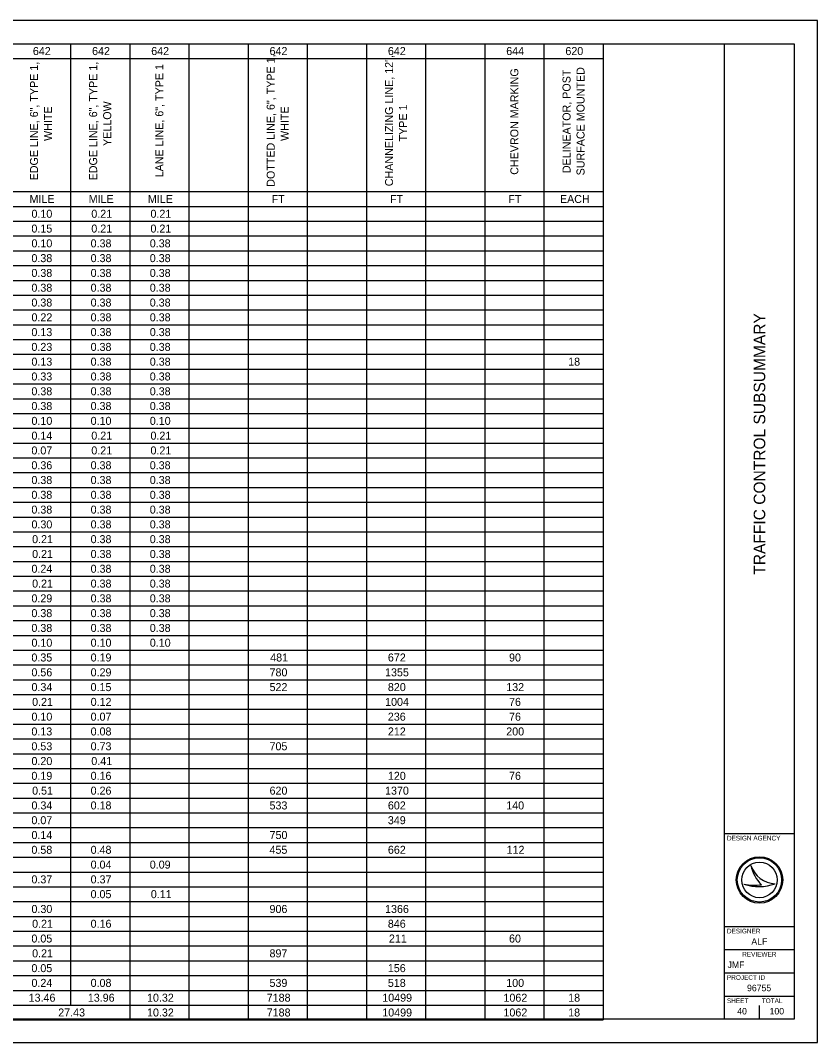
# Model space of a CAD drawing. Extents: x 0 to 34, y 0 to 22.
# Drawn here: x 16.84 to 34, y 0 to 22 of the extents above; entities that cross this region are included whole.
import ezdxf

# ---------------------------------------------------------------- set-up
doc = ezdxf.new("R2010")
doc.units = 0
for name, color, linetype in [('Default', 7, 'Continuous'), ('SH_Border', 7, 'Continuous'), ('SH_Cut_Line', 7, 'Continuous'), ('SH_Data', 7, 'Continuous')]:
    doc.layers.add(name, color=color, linetype=linetype)

msp = doc.modelspace()

# ---------------------------------------------------------------- linework, layer by layer
at = {"layer": 'Default'}
for p, q in [((1.5, 21.5), (29.385, 21.5)), ((17.924, 21.5), (17.924, 1.124)), ((19.197, 21.5), (19.197, 1.124)), ((20.471, 21.5), (20.471, 1.124)), ((21.744, 21.5), (21.744, 1.124)), ((23.018, 21.5), (23.018, 1.124)), ((24.291, 21.5), (24.291, 1.124)), ((25.565, 21.5), (25.565, 1.124)), ((26.838, 21.5), (26.838, 1.124)), ((28.112, 21.5), (28.112, 1.124)), ((29.385, 21.5), (29.385, 1.124)), ((9.01, 21.182), (29.385, 21.182)), ((9.01, 18.316), (29.385, 18.316)), ((1.5, 17.998), (29.385, 17.998)), ((10.283, 17.68), (29.385, 17.68)), ((10.283, 17.361), (29.385, 17.361)), ((10.283, 17.043), (29.385, 17.043)), ((10.283, 16.724), (29.385, 16.724)), ((10.283, 16.406), (29.385, 16.406)), ((10.283, 16.088), (29.385, 16.088)), ((10.283, 15.769), (29.385, 15.769)), ((10.283, 15.451), (29.385, 15.451)), ((10.283, 15.133), (29.385, 15.133)), ((10.283, 14.814), (29.385, 14.814)), ((10.283, 14.496), (29.385, 14.496)), ((10.283, 14.178), (29.385, 14.178)), ((10.283, 13.859), (29.385, 13.859)), ((10.283, 13.541), (29.385, 13.541)), ((10.283, 13.222), (29.385, 13.222)), ((10.283, 12.904), (29.385, 12.904)), ((10.283, 12.586), (29.385, 12.586)), ((10.283, 12.267), (29.385, 12.267)), ((10.283, 11.949), (29.385, 11.949)), ((10.283, 11.631), (29.385, 11.631)), ((10.283, 11.312), (29.385, 11.312)), ((10.283, 10.994), (29.385, 10.994)), ((10.283, 10.675), (29.385, 10.675)), ((10.283, 10.357), (29.385, 10.357)), ((10.283, 10.039), (29.385, 10.039)), ((10.283, 9.72), (29.385, 9.72)), ((10.283, 9.402), (29.385, 9.402)), ((10.283, 9.084), (29.385, 9.084)), ((10.283, 8.765), (29.385, 8.765)), ((10.283, 8.447), (29.385, 8.447)), ((10.283, 8.129), (29.385, 8.129)), ((10.283, 7.81), (29.385, 7.81)), ((10.283, 7.492), (29.385, 7.492)), ((10.283, 7.173), (29.385, 7.173)), ((10.283, 6.855), (29.385, 6.855)), ((10.283, 6.537), (29.385, 6.537)), ((10.283, 6.218), (29.385, 6.218)), ((10.283, 5.9), (29.385, 5.9)), ((10.283, 5.582), (29.385, 5.582)), ((10.283, 5.263), (29.385, 5.263)), ((10.283, 4.945), (29.385, 4.945)), ((10.283, 4.627), (29.385, 4.627)), ((10.283, 4.308), (29.385, 4.308)), ((10.283, 3.99), (29.385, 3.99)), ((10.283, 3.671), (29.385, 3.671)), ((10.283, 3.353), (29.385, 3.353)), ((10.283, 3.035), (29.385, 3.035)), ((10.283, 2.716), (29.385, 2.716)), ((10.283, 2.398), (29.385, 2.398)), ((10.283, 2.08), (29.385, 2.08)), ((10.283, 1.761), (29.385, 1.761)), ((10.283, 1.443), (29.385, 1.443)), ((1.5, 1.124), (29.385, 1.124)), ((17.924, 1.124), (17.924, 0.806)), ((19.197, 1.124), (19.197, 0.488)), ((20.471, 1.124), (20.471, 0.488)), ((21.744, 1.124), (21.744, 0.488)), ((23.018, 1.124), (23.018, 0.488)), ((24.291, 1.124), (24.291, 0.488)), ((25.565, 1.124), (25.565, 0.488)), ((26.838, 1.124), (26.838, 0.488)), ((28.112, 1.124), (28.112, 0.488)), ((29.385, 1.124), (29.385, 0.488)), ((1.5, 0.806), (29.385, 0.806)), ((1.5, 0.488), (29.385, 0.488))]:
    msp.add_line(p, q, dxfattribs=at)
at = {"layer": 'SH_Border'}
for p, q in [((32, 0.5), (32, 21.5)), ((32, 4.5), (33.5, 4.5)), ((32, 2.5), (33.5, 2.5)), ((32, 2), (33.5, 2)), ((32, 1.5), (33.5, 1.5)), ((32, 1), (33.5, 1))]:
    msp.add_line(p, q, dxfattribs=at)
msp.add_lwpolyline([(1.5, 21.5), (33.5, 21.5), (33.5, 0.5), (1.5, 0.5)], close=True, dxfattribs=at)
at = {"layer": 'SH_Cut_Line'}
msp.add_lwpolyline([(0, 0), (34, 0), (34, 22), (0, 22)], close=True, dxfattribs=at)
at = {"layer": 'SH_Data'}
for p, q in [((32.567, 3.81), (32.567, 3.81)), ((32.417, 3.41), (32.417, 3.41)), ((32.75, 3.5), (32.75, 3.5)), ((33.087, 3.419), (33.087, 3.419)), ((32.375, 0.675), (32.375, 0.675)), ((32.75, 0.5), (32.75, 0.8))]:
    msp.add_line(p, q, dxfattribs=at)
for radius in [0.5, 0.477, 0.477, 0.382]:
    msp.add_circle((32.75, 3.5), radius, dxfattribs=at)
for centre, radius, start, end in [((33.116, 3.998), 0.58, 198.9257, 198.9319), ((33.347, 3.97), 0.796, 191.6379, 191.6421), ((33.116, 3.998), 0.58, 198.9319, 267.1657), ((33.347, 3.97), 0.796, 191.6421, 226.0947), ((32.739, 4.37), 1.013, 251.4576, 290.0832), ((32.648, 4.654), 1.266, 259.4964, 259.4995), ((32.739, 4.37), 1.013, 251.4527, 251.4576), ((32.648, 4.654), 1.266, 259.4995, 276.6672)]:
    msp.add_arc(centre, radius, start, end, dxfattribs=at)

# ---------------------------------------------------------------- texts
at = {"layer": 'Default'}
for s, p in [('642', (17.112, 21.255)), ('642', (18.386, 21.255)), ('642', (19.659, 21.255)), ('642', (22.206, 21.255)), ('642', (24.753, 21.255)), ('644', (27.3, 21.255)), ('620', (28.573, 21.255)), ('MILE', (17.04, 18.071)), ('MILE', (18.314, 18.071)), ('MILE', (19.587, 18.071)), ('FT', (22.251, 18.071)), ('FT', (24.798, 18.071)), ('FT', (27.345, 18.071)), ('EACH', (28.456, 18.071)), ('0.10', (17.082, 17.753)), ('0.21', (18.37, 17.753)), ('0.21', (19.643, 17.753)), ('0.15', (17.081, 17.434)), ('0.21', (18.37, 17.434)), ('0.21', (19.643, 17.434)), ('0.10', (17.082, 17.116)), ('0.38', (18.355, 17.116)), ('0.38', (19.628, 17.116)), ('0.38', (17.081, 16.798)), ('0.38', (18.355, 16.798)), ('0.38', (19.628, 16.798)), ('0.38', (17.081, 16.479)), ('0.38', (18.355, 16.479)), ('0.38', (19.628, 16.479)), ('0.38', (17.081, 16.161)), ('0.38', (18.355, 16.161)), ('0.38', (19.628, 16.161)), ('0.38', (17.081, 15.842)), ('0.38', (18.355, 15.842)), ('0.38', (19.628, 15.842)), ('0.22', (17.082, 15.524)), ('0.38', (18.355, 15.524)), ('0.38', (19.628, 15.524)), ('0.13', (17.081, 15.206)), ('0.38', (18.355, 15.206)), ('0.38', (19.628, 15.206)), ('0.23', (17.081, 14.887)), ('0.38', (18.355, 14.887)), ('0.38', (19.628, 14.887)), ('0.13', (17.081, 14.569)), ('0.38', (18.355, 14.569)), ('0.38', (19.628, 14.569)), ('18', (28.633, 14.569)), ('0.33', (17.081, 14.251)), ('0.38', (18.355, 14.251)), ('0.38', (19.628, 14.251)), ('0.38', (17.081, 13.932)), ('0.38', (18.355, 13.932)), ('0.38', (19.628, 13.932)), ('0.38', (17.081, 13.614)), ('0.38', (18.355, 13.614)), ('0.38', (19.628, 13.614)), ('0.10', (17.082, 13.295)), ('0.10', (18.355, 13.295)), ('0.10', (19.629, 13.295)), ('0.14', (17.082, 12.977)), ('0.21', (18.37, 12.977)), ('0.21', (19.643, 12.977)), ('0.07', (17.081, 12.659)), ('0.21', (18.37, 12.659)), ('0.21', (19.643, 12.659)), ('0.36', (17.081, 12.34)), ('0.38', (18.355, 12.34)), ('0.38', (19.628, 12.34)), ('0.38', (17.081, 12.022)), ('0.38', (18.355, 12.022)), ('0.38', (19.628, 12.022)), ('0.38', (17.081, 11.704)), ('0.38', (18.355, 11.704)), ('0.38', (19.628, 11.704)), ('0.38', (17.081, 11.385)), ('0.38', (18.355, 11.385)), ('0.38', (19.628, 11.385)), ('0.30', (17.082, 11.067)), ('0.38', (18.355, 11.067)), ('0.38', (19.628, 11.067)), ('0.21', (17.096, 10.749)), ('0.38', (18.355, 10.749)), ('0.38', (19.628, 10.749)), ('0.21', (17.096, 10.43)), ('0.38', (18.355, 10.43)), ('0.38', (19.628, 10.43)), ('0.24', (17.082, 10.112)), ('0.38', (18.355, 10.112)), ('0.38', (19.628, 10.112)), ('0.21', (17.096, 9.793)), ('0.38', (18.355, 9.793)), ('0.38', (19.628, 9.793)), ('0.29', (17.081, 9.475)), ('0.38', (18.355, 9.475)), ('0.38', (19.628, 9.475)), ('0.38', (17.081, 9.157)), ('0.38', (18.355, 9.157)), ('0.38', (19.628, 9.157)), ('0.38', (17.081, 8.838)), ('0.38', (18.355, 8.838)), ('0.38', (19.628, 8.838)), ('0.10', (17.082, 8.52)), ('0.10', (18.355, 8.52)), ('0.10', (19.629, 8.52)), ('0.35', (17.081, 8.202)), ('0.19', (18.355, 8.202)), ('481', (22.22, 8.202)), ('672', (24.753, 8.202)), ('90', (27.36, 8.202)), ('0.56', (17.081, 7.883)), ('0.29', (18.355, 7.883)), ('780', (22.206, 7.883)), ('1355', (24.692, 7.883)), ('0.34', (17.082, 7.565)), ('0.15', (18.354, 7.565)), ('522', (22.206, 7.565)), ('820', (24.753, 7.565)), ('132', (27.3, 7.565)), ('0.21', (17.096, 7.246)), ('0.12', (18.356, 7.246)), ('1004', (24.693, 7.246)), ('76', (27.36, 7.246)), ('0.10', (17.082, 6.928)), ('0.07', (18.355, 6.928)), ('236', (24.752, 6.928)), ('76', (27.36, 6.928)), ('0.13', (17.081, 6.61)), ('0.08', (18.355, 6.61)), ('212', (24.753, 6.61)), ('200', (27.3, 6.61)), ('0.53', (17.081, 6.291)), ('0.73', (18.355, 6.291)), ('705', (22.205, 6.291)), ('0.20', (17.082, 5.973)), ('0.41', (18.37, 5.973)), ('0.19', (17.081, 5.655)), ('0.16', (18.355, 5.655)), ('120', (24.753, 5.655)), ('76', (27.36, 5.655)), ('0.51', (17.096, 5.336)), ('0.26', (18.355, 5.336)), ('620', (22.206, 5.336)), ('1370', (24.692, 5.336)), ('0.34', (17.082, 5.018)), ('0.18', (18.355, 5.018)), ('533', (22.205, 5.018)), ('602', (24.753, 5.018)), ('140', (27.3, 5.018)), ('0.07', (17.081, 4.7)), ('349', (24.752, 4.7)), ('0.14', (17.082, 4.381)), ('750', (22.206, 4.381)), ('0.58', (17.081, 4.063)), ('0.48', (18.355, 4.063)), ('455', (22.205, 4.063)), ('662', (24.753, 4.063)), ('112', (27.308, 4.063)), ('0.04', (18.355, 3.744)), ('0.09', (19.628, 3.744)), ('0.37', (17.081, 3.426)), ('0.37', (18.355, 3.426)), ('0.05', (18.354, 3.108)), ('0.11', (19.651, 3.108)), ('0.30', (17.082, 2.789)), ('906', (22.205, 2.789)), ('1366', (24.692, 2.789)), ('0.21', (17.096, 2.471)), ('0.16', (18.355, 2.471)), ('846', (24.752, 2.471)), ('0.05', (17.081, 2.153)), ('211', (24.775, 2.153)), ('60', (27.36, 2.153)), ('0.21', (17.096, 1.834)), ('897', (22.205, 1.834)), ('0.05', (17.081, 1.516)), ('156', (24.752, 1.516)), ('0.24', (17.082, 1.198)), ('0.08', (18.355, 1.198)), ('539', (22.205, 1.198)), ('518', (24.752, 1.198)), ('100', (27.3, 1.198)), ('13.46', (17.021, 0.879)), ('13.96', (18.295, 0.879)), ('10.32', (19.569, 0.879)), ('7188', (22.145, 0.879)), ('10499', (24.632, 0.879)), ('1062', (27.24, 0.879)), ('18', (28.633, 0.879)), ('27.43', (17.658, 0.561)), ('10.32', (19.569, 0.561)), ('7188', (22.145, 0.561)), ('10499', (24.632, 0.561)), ('1062', (27.24, 0.561)), ('18', (28.633, 0.561))]:
    msp.add_text(s, height=0.1723, dxfattribs=at).set_placement(p)
for s, height, p in [('DOTTED LINE, 6", TYPE 1, ', 0.17229, (22.317, 18.42)), ('CHANNELIZING LINE, 12", ', 0.17229, (24.864, 18.432)), ('EDGE LINE, 6", TYPE 1, ', 0.17229, (17.223, 18.558)), ('EDGE LINE, 6", TYPE 1, ', 0.17229, (18.496, 18.558)), ('LANE LINE, 6", TYPE 1', 0.17229, (19.92, 18.623)), ('CHEVRON MARKING', 0.17229, (27.561, 18.678)), ('DELINEATOR, POST ', 0.17229, (28.684, 18.714)), ('SURFACE MOUNTED', 0.17229, (28.985, 18.665)), ('YELLOW', 0.1723, (18.798, 19.299)), ('WHITE', 0.1723, (17.524, 19.406)), ('WHITE', 0.1723, (22.618, 19.406)), ('TYPE 1', 0.1723, (25.165, 19.396))]:
    msp.add_text(s, height=height, rotation=90, dxfattribs=at).set_placement(p)
at = {"layer": 'SH_Data'}
msp.add_text('TRAFFIC CONTROL SUBSUMMARY', height=0.25, rotation=90, dxfattribs=at).set_placement((32.875, 10.071))
for s, height, p in [('DESIGN AGENCY', 0.1, (32.05, 4.35)), ('DESIGNER', 0.1, (32.05, 2.35)), ('ALF', 0.14, (32.575, 2.105)), ('REVIEWER', 0.1, (32.378, 1.85)), ('JMF', 0.14, (32.064, 1.605)), ('PROJECT ID', 0.1, (32.05, 1.35)), ('96755', 0.14, (32.482, 1.105)), ('SHEET', 0.1, (32.05, 0.85)), ('TOTAL', 0.1, (32.8, 0.85)), ('40', 0.14, (32.271, 0.605)), ('100', 0.14, (32.967, 0.605))]:
    msp.add_text(s, height=height, dxfattribs=at).set_placement(p)

doc.saveas('drawing.dxf')
